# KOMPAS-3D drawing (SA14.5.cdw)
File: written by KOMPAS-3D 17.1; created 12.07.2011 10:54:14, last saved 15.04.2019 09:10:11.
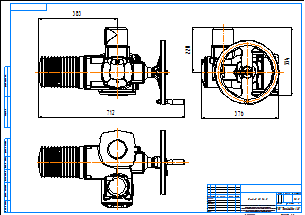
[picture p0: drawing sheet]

Title block, sheet 1: name: Привод SA 14.5; material: Внимание! Данный продукт является объектом авторского права ООО «Торговый Дом АДЛ». / Запрещается изменение, копирование, распространение / (в том числе путем копирования на другие сайты и ресурсы в Интернете) / или любое иное использование информации и объектов без предварительного / согласия правообладателя (ООО «Торговый Дом АДЛ»).; scale: 1:2,5; sheets: 1; organisation: ООО "Торговый дом АДЛ"; sheet format: A2; stored path: \\adlc.lan\data\АДЛ_ПКД\3D-модели\Поставщики\Сервоприводы AUMA\Электроприводы серии SA\KOMPAS 2D\Привод SA 14.5.cdw

Views: Проекционный вид 2, Проекционный вид 4, Проекционный вид 6
Dimensions and other numbers on the sheet: 376; 334; 220; 712; 383; 1:2,5; 1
